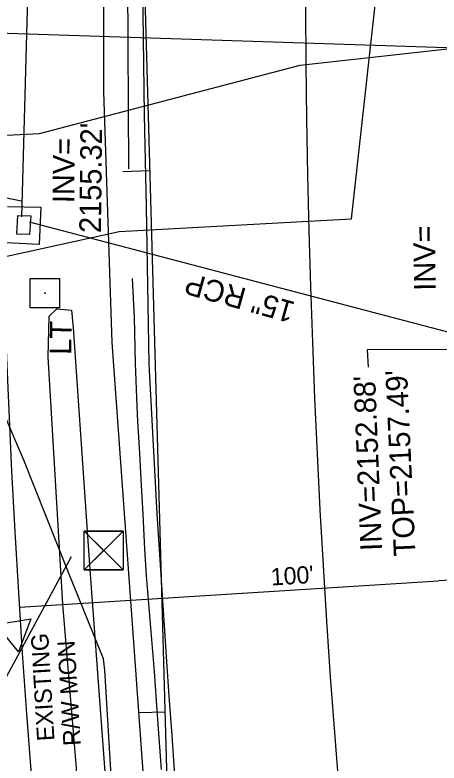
# Model space of a CAD drawing. Extents: x 945964 to 948456, y 631061 to 636061.
# Drawn here: x 946755.3 to 946833.7, y 632730.8 to 632869 of the extents above; entities that cross this region are included whole.
import ezdxf

# ---------------------------------------------------------------- set-up
doc = ezdxf.new("R2010")
doc.units = 0
for name, color, linetype in [('CTL Bench Mark CELL', 7, 'Continuous'), ('Exist Boundary County Line', 7, 'Continuous'), ('Exist Guardrail', 7, 'Continuous'), ('Exist Horizontal Alignment', 7, 'Continuous'), ('Exist Horizontal Baseline Alignment', 7, 'Continuous'), ('Exist Horizontal Baseline Alignment Tick small', 7, 'Continuous'), ('Exist Other Culture Area Outline', 7, 'Continuous'), ('Exist Right of Way Line', 7, 'Continuous'), ('Exist Right of Way Monument CELL', 7, 'Continuous'), ('Exist Right of Way Monument Text', 7, 'Continuous'), ('Exist Right of Way Width CELL', 7, 'Continuous'), ('Exist Roads Curbs', 7, 'Continuous'), ('Exist Roads EOP', 7, 'Continuous'), ('Exist Structure Minor Catch Basin Top Elevation', 7, 'Continuous'), ('Exist Structure Minor Drop Inlet', 7, 'Continuous'), ('Exist Structure Minor Pipes RCP 15 Inch', 7, 'Continuous'), ('Exist Structure Minor Pipes RCP 15 Inch Invert', 7, 'Continuous'), ('Exist Structure Minor Pipes RCP 15 Inch Text', 7, 'Continuous'), ('Exist Structure Minor Pipes RCP 24 Inch Invert', 7, 'Continuous'), ('Exist Utilities Other Pole With Base CELL', 7, 'Continuous'), ('Exist Utilities Other Pole With Base Text', 7, 'Continuous'), ('Exist Utilities Telephone UG Cable SUE', 7, 'Continuous'), ('Exist Utilities Water UG Line SUE', 7, 'Continuous'), ('Exist Vegetation Hedge Row', 7, 'Continuous'), ('Scratch_Level_5', 7, 'Continuous')]:
    doc.layers.add(name, color=color, linetype=linetype)

# ---------------------------------------------------------------- blocks, each defined once
blk = doc.blocks.new('CTL BENCH MARK')
at = {"layer": 'CTL Bench Mark CELL'}
blk.add_line((0, 0), (0, 0), dxfattribs=at)
blk.add_lwpolyline([(-0.072, 0.07175), (0.07175, 0.07175), (0.07175, -0.072), (-0.072, -0.072)], close=True, dxfattribs=at)
for points in [[(0.07175, 0.07175), (-0.072, -0.072), (-0.000125, -0.000125), (0.07175, -0.072), (-0.072, 0.07175)], [(-0.000125, -0.000125), (0.07175, 0.07175), (-0.072, 0.07175), (-0.000125, -0.000125)], [(-0.000125, -0.000125), (-0.072, -0.072), (0.07175, -0.072), (-0.000125, -0.000125)]]:
    blk.add_lwpolyline(points, dxfattribs=at)

msp = doc.modelspace()

# ---------------------------------------------------------------- linework, layer by layer
at = {"layer": 'Exist Boundary County Line'}
msp.add_line((946708.83, 632867.13), (946851.45, 632862.43), dxfattribs=at)
at = {"layer": 'Exist Guardrail'}
msp.add_lwpolyline([(946786.09, 632606.02), (946784.11, 632618.62), (946779.5, 632652.76), (946776.8, 632680.24), (946773.62, 632720.28), (946771.95, 632747.96), (946771.7, 632750.05), (946765.22, 632765.95), (946756.97, 632786.73), (946749.63, 632803.73), (946744.23, 632816.47)], dxfattribs=at)
at = {"layer": 'Exist Horizontal Alignment'}
msp.add_arc((948718.82, 632879.65), 1909.86, 158.53343, 198.31343, dxfattribs=at)
at = {"layer": 'Exist Horizontal Baseline Alignment'}
msp.add_line((946785.93, 632640.23), (946772.39, 633118.89), dxfattribs=at)
at = {"layer": 'Exist Horizontal Baseline Alignment Tick small'}
for p, q in [((946780.28, 632840.15), (946775.28, 632840.01)), ((946783.11, 632740.19), (946778.11, 632740.05))]:
    msp.add_line(p, q, dxfattribs=at)
at = {"layer": 'Exist Other Culture Area Outline'}
msp.add_lwpolyline([(946754, 632833.6), (946760.13, 632833.45), (946759.79, 632826.57), (946753.67, 632826.9)], dxfattribs=at)
at = {"layer": 'Exist Right of Way Line'}
msp.add_arc((948848.33, 632890.69), 2096.28, 158.90258, 198.31343, dxfattribs=at)
at = {"layer": 'Exist Right of Way Monument CELL'}
msp.add_line((946755.39, 632755.05), (946755.39, 632755.05), dxfattribs=at)
msp.add_lwpolyline([(946751.87, 632756.38), (946758.3, 632757.42), (946755.98, 632751.34)], close=True, dxfattribs=at)
at = {"layer": 'Exist Right of Way Width CELL'}
for p in [(946855.96, 632765.85), (946756.16, 632759.59)]:
    msp.add_line(p, (946833.58, 632764.44), dxfattribs=at)
at = {"layer": 'Exist Roads Curbs'}
for points in [[(946761.58, 633011.22), (946766.94, 633011.66), (946770.66, 633010.49), (946767.28, 633007.52), (946773.56, 633001.31), (946777.16, 633004.52), (946778.87, 633000.8), (946779.34, 632996.45), (946779.24, 632989.33), (946778.73, 632980.85), (946777.79, 632955.88), (946776.46, 632909.28), (946776.12, 632875.07), (946776.32, 632840.58)], [(946777, 632820.3), (946777.36, 632813.1), (946777.58, 632804.67), (946777.81, 632798.23), (946777.99, 632793.85), (946778.34, 632788.03), (946778.61, 632783.13), (946778.98, 632776.77), (946779.27, 632770.29), (946779.6, 632765.42), (946780.48, 632754.32), (946781.07, 632747.67), (946781.4, 632742.29), (946781.91, 632735.45), (946782.36, 632729.58)]]:
    msp.add_lwpolyline(points, dxfattribs=at)
at = {"layer": 'Exist Roads EOP'}
msp.add_lwpolyline([(946778.79, 632883.34), (946779.22, 632850.59), (946779.6, 632833.51), (946780.05, 632804.54), (946781.57, 632776.84), (946783.34, 632749.53), (946783.75, 632743.13), (946784.34, 632735.87), (946784.75, 632729.45), (946785.15, 632724.02), (946785.67, 632718.16), (946786.06, 632713.81), (946786.33, 632709.8), (946787.19, 632699.99), (946788.15, 632690.29), (946789.01, 632682.01), (946790.04, 632672.28), (946791.13, 632661.42), (946792.08, 632653.67), (946793.21, 632644.97), (946794.29, 632636.17), (946795.44, 632626.85), (946796.65, 632617.54), (946798.85, 632600.3)], dxfattribs=at)
at = {"layer": 'Exist Structure Minor Drop Inlet'}
msp.add_line((946755.85, 632831.9), (946758.25, 632831.85), dxfattribs=at)
msp.add_lwpolyline([(946758.25, 632831.85), (946758.06, 632828.39), (946755.69, 632828.46), (946755.85, 632831.9)], dxfattribs=at)
at = {"layer": 'Exist Structure Minor Pipes RCP 15 Inch'}
for p, q in [((946756.59, 632831.69), (946761.42, 633000.91)), ((946840.39, 632809.01), (946758.05, 632830.67))]:
    msp.add_line(p, q, dxfattribs=at)
at = {"layer": 'Exist Structure Minor Pipes RCP 24 Inch Invert'}
for points in [[(946756.47, 632834.6), (946729.82, 632840.13), (946729.84, 632843.55)], [(946840.09, 632807.2), (946820.39, 632807.13), (946820.56, 632803.9)]]:
    msp.add_lwpolyline(points, dxfattribs=at)
at = {"layer": 'Exist Utilities Other Pole With Base CELL'}
msp.add_line((946760.9, 632817.59), (946760.9, 632817.59), dxfattribs=at)
msp.add_lwpolyline([(946758.17, 632820.29), (946763.57, 632820.29), (946763.57, 632814.89), (946758.17, 632814.89), (946758.17, 632820.29)], dxfattribs=at)
msp.add_circle((946760.9, 632817.59), 0.0707, dxfattribs=at)
at = {"layer": 'Exist Utilities Telephone UG Cable SUE'}
for points in [[(946641.97, 632809.2), (946660.11, 632804.07), (946680.18, 632808.2), (946774.58, 632828.99), (946817.48, 632831.3), (946823.43, 632884.78), (946845.89, 632888.04), (946847.42, 632888.16), (946852.01, 632876.88), (946848.99, 632861.62)], [(946636.81, 632795.11), (946643.64, 632789.82), (946680.82, 632821.06), (946727, 632845.41), (946759.9, 632847.07), (946808.05, 632859.72), (946846.96, 632864.02), (946847.96, 632862.19)]]:
    msp.add_lwpolyline(points, dxfattribs=at)
at = {"layer": 'Exist Utilities Water UG Line SUE'}
msp.add_lwpolyline([(946788.6, 632630.18), (946781.16, 632699.34), (946773.28, 632808.46), (946771.79, 632854.84), (946771.8, 632932.21), (946773, 633009.71), (946780.55, 633091.42), (946784.9, 633156.63), (946798.66, 633233.47), (946810, 633290.7), (946821.3, 633337.55), (946829.57, 633363.16), (946855.21, 633460.81), (946878.65, 633533.2), (946897.38, 633594.69), (946885.48, 633607.31), (946857.92, 633638.18)], dxfattribs=at)
at = {"layer": 'Exist Vegetation Hedge Row'}
msp.add_lwpolyline([(946777.44, 632626.3), (946772.59, 632655.07), (946768.68, 632697.03), (946766.71, 632729.81), (946764.2, 632760.14), (946761.46, 632805.84), (946761.66, 632813.33), (946763.11, 632814.67), (946765.8, 632814.42), (946766.12, 632811.2), (946769.19, 632766.44), (946772.8, 632717.52), (946777.27, 632659.19), (946782.33, 632619.48)], dxfattribs=at)
at = {"layer": 'Scratch_Level_5'}
msp.add_line((946765.74, 632768.87), (946694.09, 632636.66), dxfattribs=at)

# ---------------------------------------------------------------- block references
at = {"layer": 'CTL Bench Mark CELL', "xscale": 50, "yscale": 50}
msp.add_blockref('CTL BENCH MARK', (946771.75, 632770.04), dxfattribs=at)

# ---------------------------------------------------------------- texts
at = {"layer": 'Exist Right of Way Monument Text'}
for s, p in [('EXISTING', (946762.65, 632734.93)), ('R/W MON', (946767.51, 632734.05))]:
    msp.add_text(s, height=3.2, rotation=93.3847, dxfattribs=at).set_placement(p)
at = {"layer": 'Exist Right of Way Width CELL'}
msp.add_text("100'", height=3.2, rotation=3.5856, dxfattribs=at).set_placement((946802.69, 632763.56))
at = {"layer": 'Exist Structure Minor Catch Basin Top Elevation'}
msp.add_text("TOP=2157.49'", height=4, rotation=92.6464, dxfattribs=at).set_placement((946829.34, 632769.06))
at = {"layer": 'Exist Structure Minor Pipes RCP 15 Inch Invert'}
for s, rotation, p in [("2155.32'", 89.3628, (946771.23, 632828.68)), ('INV=', 89.3628, (946766.28, 632834.19)), ("INV=2152.88'", 92.3279, (946823.17, 632770.05))]:
    msp.add_text(s, height=4, rotation=rotation, dxfattribs=at).set_placement(p)
at = {"layer": 'Exist Structure Minor Pipes RCP 15 Inch Text'}
msp.add_text('15" RCP', height=4, rotation=164.4405, dxfattribs=at).set_placement((946807.31, 632815.86))
at = {"layer": 'Exist Structure Minor Pipes RCP 24 Inch Invert'}
msp.add_text('INV=', height=4, rotation=90.8413, dxfattribs=at).set_placement((946833.07, 632818.05))
at = {"layer": 'Exist Utilities Other Pole With Base Text'}
msp.add_text('LT', height=4, rotation=89.1171, dxfattribs=at).set_placement((946765.73, 632806.17))

doc.saveas('drawing.dxf')
